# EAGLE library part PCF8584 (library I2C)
I2C-Controuler
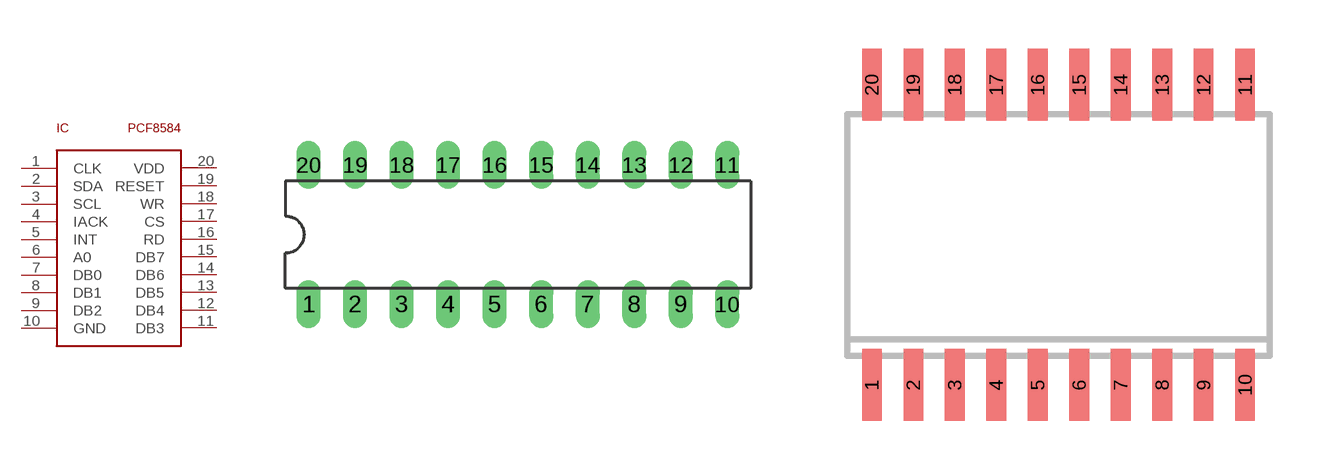
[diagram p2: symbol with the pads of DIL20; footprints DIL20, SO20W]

Designator prefix IC

## PCF8584P  [DIL20]
1  CLK  in
2  SDA
3  SCL
4  IACK  in
5  INT  out
6  A0  in
7  DB0
8  DB1
9  DB2
10  GND  pwr
11  DB3
12  DB4
13  DB5
14  DB6
15  DB7
16  RD
17  CS  in
18  WR  in
19  RESET
20  VDD  pwr

## PCF8584T  [SO20W]
Pads as for DIL20

## Footprint DIL20 (pad centres in mm)
Dual In Line Package
drill 0.813 long: 1 -11.43,-3.81; 2 -8.89,-3.81; 3 -6.35,-3.81; 4 -3.81,-3.81; 5 -1.27,-3.81; 6 1.27,-3.81; 7 3.81,-3.81; 8 6.35,-3.81; 9 8.89,-3.81; 10 11.43,-3.81; 11 11.43,3.81; 12 8.89,3.81; 13 6.35,3.81; 14 3.81,3.81; 15 1.27,3.81; 16 -1.27,3.81; 17 -3.81,3.81; 18 -6.35,3.81; 19 -8.89,3.81; 20 -11.43,3.81

## Footprint SO20W (pad centres in mm)
SMALL OUTLINE INTEGRATED CIRCUIT wide body 7.5 mm/JEDEC MS-013AC
smd 0.6 x 2.2: 1 -5.715,-4.6; 2 -4.445,-4.6; 3 -3.175,-4.6; 4 -1.905,-4.6; 5 -0.635,-4.6; 6 0.635,-4.6; 7 1.905,-4.6; 8 3.175,-4.6; 9 4.445,-4.6; 10 5.715,-4.6; 11 5.715,4.6; 12 4.445,4.6; 13 3.175,4.6; 14 1.905,4.6; 15 0.635,4.6; 16 -0.635,4.6; 17 -1.905,4.6; 18 -3.175,4.6; 19 -4.445,4.6; 20 -5.715,4.6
